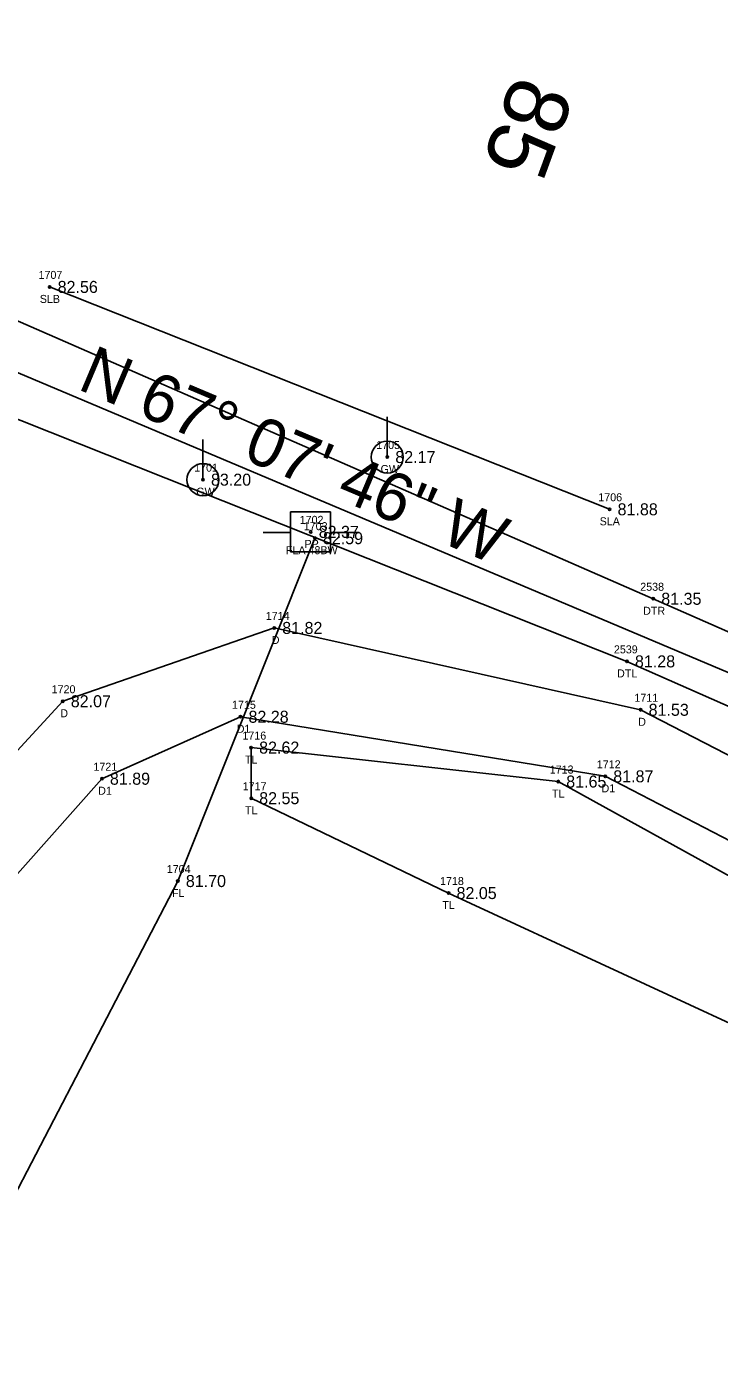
# Model space of a CAD drawing. Extents: x 2139392 to 2143384, y 505395 to 510520.
# Drawn here: x 2141208.9 to 2141295.5, y 509433.7 to 509599 of the extents above; entities that cross this region are included whole.
import ezdxf

# ---------------------------------------------------------------- set-up
doc = ezdxf.new("R2010")
doc.units = 0
for name, color, linetype in [('RD_EX_Driveway', 7, 'Continuous'), ('RD_EX_Driveway_txCode', 7, 'Continuous'), ('RD_EX_Fence_Other', 7, 'Continuous'), ('RD_EX_Fence_Other_txCode', 7, 'Continuous'), ('RD_EX_H2O', 7, 'Continuous'), ('RD_EX_H2O_txCode', 7, 'Continuous'), ('RD_EX_TX_Driveway_ELEV', 7, 'Continuous'), ('RD_EX_TX_Fence_Other_ELEV', 7, 'Continuous'), ('RD_EX_TX_H2O_ELEV', 7, 'Continuous'), ('RD_EX_TX_UT_ELEV', 7, 'Continuous'), ('RD_EX_TX_VEG_ELEV', 7, 'Continuous'), ('RD_EX_UT', 7, 'Continuous'), ('RD_EX_UT_txCode', 7, 'Continuous'), ('RD_EX_VEG', 7, 'Continuous'), ('RD_EX_VEG_txCode', 7, 'Continuous'), ('RD_HC_Cl', 7, 'Continuous'), ('RD_HC_Data', 7, 'Continuous'), ('RD_HC_Survey_ELEV', 7, 'Continuous'), ('RD_HC_TX_Sta50', 7, 'Continuous'), ('RD_SMD_Locator', 7, 'Continuous')]:
    doc.layers.add(name, color=color, linetype=linetype)

msp = doc.modelspace()

# ---------------------------------------------------------------- linework, layer by layer
at = {"layer": 'RD_EX_Driveway'}
for points in [[(2141336.23, 509487.56), (2141285.67, 509513.64), (2141239.88, 509523.87), (2141213.45, 509514.71), (2141179.64, 509478.01), (2141153.77, 509441.85), (2141133.3, 509434.61)], [(2141332.97, 509478.52), (2141281.25, 509505.33), (2141235.66, 509512.77), (2141218.34, 509505.03), (2141189.33, 509472.4), (2141162.86, 509430.93), (2141143.61, 509418.42), (2141126.3, 509420.24)]]:
    msp.add_lwpolyline(points, dxfattribs=at)
at = {"layer": 'RD_EX_Fence_Other'}
msp.add_lwpolyline([(2141244.96, 509535.08), (2141227.83, 509492.25), (2141166.83, 509374.98), (2141164.26, 509373.91), (2141120.57, 509389.85)], dxfattribs=at)
at = {"layer": 'RD_EX_H2O'}
for points in [[(2141186.59, 509558.37), (2141283.96, 509519.69), (2141328.71, 509499.95), (2141337.07, 509500.38), (2141376.25, 509551.14), (2141424.64, 509618.25), (2141430.55, 509633.85)], [(2141191.18, 509569.46), (2141287.25, 509527.51), (2141331.23, 509508.17), (2141369.45, 509556.75), (2141417.65, 509623.04), (2141430.55, 509633.85)]]:
    msp.add_lwpolyline(points, dxfattribs=at)
at = {"layer": 'RD_EX_UT'}
for p, q in [((2141254.01, 509545.22), (2141254.01, 509550.22)), ((2141230.97, 509542.39), (2141230.97, 509547.39)), ((2141246.93, 509538.38), (2141241.93, 509538.38)), ((2141241.93, 509538.38), (2141241.93, 509533.38)), ((2141246.93, 509533.38), (2141246.93, 509538.38)), ((2141238.5, 509535.81), (2141241.97, 509535.81)), ((2141246.86, 509535.81), (2141250.5, 509535.81)), ((2141241.93, 509533.38), (2141246.93, 509533.38))]:
    msp.add_line(p, q, dxfattribs=at)
for centre in [(2141254.01, 509545.22), (2141230.97, 509542.39)]:
    msp.add_circle(centre, 2, dxfattribs=at)
at = {"layer": 'RD_EX_VEG'}
msp.add_line((2141281.79, 509538.69), (2141211.81, 509566.47), dxfattribs=at)
msp.add_lwpolyline([(2141330.29, 509474.35), (2141275.37, 509504.68), (2141236.99, 509508.92), (2141237, 509502.6), (2141261.66, 509490.75), (2141305.23, 509470.58)], dxfattribs=at)
at = {"layer": 'RD_HC_Cl'}
msp.add_line((2141333.39, 509502.79), (2141150.13, 509580.09), dxfattribs=at)
at = {"layer": 'RD_SMD_Locator'}
for centre in [(2141211.81, 509566.47), (2141254.01, 509545.22), (2141230.97, 509542.39), (2141281.79, 509538.69), (2141244.44, 509535.87), (2141244.96, 509535.08), (2141287.25, 509527.51), (2141239.88, 509523.87), (2141283.96, 509519.69), (2141213.45, 509514.71), (2141285.67, 509513.64), (2141235.66, 509512.77), (2141236.99, 509508.92), (2141281.25, 509505.33), (2141218.34, 509505.03), (2141275.37, 509504.68), (2141237, 509502.6), (2141227.83, 509492.25), (2141261.66, 509490.75)]:
    msp.add_circle(centre, 0.15, dxfattribs=at)

# ---------------------------------------------------------------- texts
at = {"layer": 'RD_EX_Driveway_txCode'}
for s, p in [('1714', (2141238.82, 509524.87)), ('D', (2141239.57, 509521.87)), ('1720', (2141212.06, 509515.71)), ('1711', (2141284.89, 509514.64)), ('D', (2141213.14, 509512.71)), ('1715', (2141234.6, 509513.77)), ('D', (2141285.37, 509511.64)), ('D1', (2141235.19, 509510.77)), ('1721', (2141217.28, 509506.03)), ('1712', (2141280.19, 509506.33)), ('D1', (2141217.87, 509503.03)), ('D1', (2141280.78, 509503.33))]:
    msp.add_text(s, height=1, dxfattribs=at).set_placement(p)
at = {"layer": 'RD_EX_Fence_Other_txCode'}
for s, p in [('1703', (2141243.57, 509536.08)), ('FLA 48BW', (2141241.34, 509533.08)), ('1704', (2141226.45, 509493.25)), ('FL', (2141227.1, 509490.25))]:
    msp.add_text(s, height=1, dxfattribs=at).set_placement(p)
at = {"layer": 'RD_EX_H2O_txCode'}
for s, p in [('2538', (2141285.62, 509528.51)), ('DTR', (2141285.98, 509525.51)), ('2539', (2141282.33, 509520.69)), ('DTL', (2141282.72, 509517.69))]:
    msp.add_text(s, height=1, dxfattribs=at).set_placement(p)
at = {"layer": 'RD_EX_TX_Driveway_ELEV'}
for s, p in [('81.82', (2141240.88, 509523.12)), ('82.07', (2141214.45, 509513.96)), ('82.28', (2141236.66, 509512.02)), ('81.53', (2141286.67, 509512.89)), ('81.89', (2141219.34, 509504.28)), ('81.87', (2141282.25, 509504.58))]:
    msp.add_text(s, height=1.5, dxfattribs=at).set_placement(p)
at = {"layer": 'RD_EX_TX_Fence_Other_ELEV'}
for s, p in [('82.59', (2141245.96, 509534.33)), ('81.70', (2141228.83, 509491.5))]:
    msp.add_text(s, height=1.5, dxfattribs=at).set_placement(p)
at = {"layer": 'RD_EX_TX_H2O_ELEV'}
for s, p in [('81.35', (2141288.25, 509526.76)), ('81.28', (2141284.96, 509518.94))]:
    msp.add_text(s, height=1.5, dxfattribs=at).set_placement(p)
at = {"layer": 'RD_EX_TX_UT_ELEV'}
for s, p in [('82.17', (2141255.01, 509544.47)), ('83.20', (2141231.97, 509541.64))]:
    msp.add_text(s, height=1.5, dxfattribs=at).set_placement(p)
at = {"layer": 'RD_EX_TX_VEG_ELEV'}
for s, p in [('82.56', (2141212.81, 509565.72)), ('81.88', (2141282.79, 509537.94)), ('82.62', (2141237.99, 509508.17)), ('81.65', (2141276.37, 509503.93)), ('82.55', (2141238, 509501.85)), ('82.05', (2141262.66, 509490))]:
    msp.add_text(s, height=1.5, dxfattribs=at).set_placement(p)
at = {"layer": 'RD_EX_UT_txCode'}
for s, p in [('1705', (2141252.62, 509546.22)), ('1701', (2141229.87, 509543.39)), ('GW', (2141253.17, 509543.22)), ('GW', (2141230.13, 509540.39)), ('1702', (2141243.06, 509536.87)), ('PP', (2141243.66, 509533.87))]:
    msp.add_text(s, height=1, dxfattribs=at).set_placement(p)
at = {"layer": 'RD_EX_VEG_txCode'}
for s, p in [('1707', (2141210.42, 509567.47)), ('SLB', (2141210.58, 509564.47)), ('1706', (2141280.38, 509539.69)), ('SLA', (2141280.55, 509536.69)), ('1716', (2141235.9, 509509.92)), ('TL', (2141236.22, 509506.92)), ('1713', (2141274.31, 509505.68)), ('1717', (2141235.94, 509503.6)), ('TL', (2141274.6, 509502.68)), ('TL', (2141236.23, 509500.6)), ('1718', (2141260.6, 509491.75)), ('TL', (2141260.89, 509488.75))]:
    msp.add_text(s, height=1, dxfattribs=at).set_placement(p)
at = {"layer": 'RD_HC_Data'}
msp.add_text('N 67%%d 07\' 46" W', height=6, rotation=337.1294, dxfattribs=at).set_placement((2141215.13, 509553.76))
at = {"layer": 'RD_HC_Survey_ELEV'}
msp.add_text('82.37', height=1.5, dxfattribs=at).set_placement((2141245.44, 509535.12))
at = {"layer": 'RD_HC_TX_Sta50'}
msp.add_text('85', height=8, rotation=249.9158, dxfattribs=at).set_placement((2141269.9, 509593.18))

doc.saveas('drawing.dxf')
